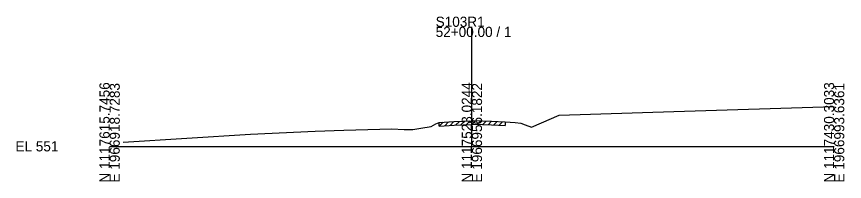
# Model space of a CAD drawing. Extents: x -26 to 203, y -10 to 12018.
# Drawn here: x -25.7 to 202.8, y 490.3 to 535.8 of the extents above; entities that cross this region are included whole.
import ezdxf

# ---------------------------------------------------------------- set-up
doc = ezdxf.new("R2010")
doc.units = 0
for name, color, linetype in [('Level 60', 7, 'Continuous'), ('Level 61', 7, 'Continuous'), ('Level 63', 7, 'Continuous')]:
    doc.layers.add(name, color=color, linetype=linetype)

msp = doc.modelspace()

# ---------------------------------------------------------------- linework, layer by layer
at = {"layer": 'Level 60'}
for p, q in [((155.79, 509.61), (200, 511)), ((119.19, 506.49), (124.1, 508.61)), ((124.1, 508.61), (155.79, 509.61)), ((85.87, 505), (88.79, 505.51)), ((88.79, 505.51), (90.06, 506.19)), ((90.06, 506.19), (90.99, 506.61)), ((90.99, 506.61), (95.14, 506.83)), ((95.14, 506.83), (100, 507.07)), ((100, 507.07), (100.44, 507.09)), ((100.44, 507.09), (105.43, 506.91)), ((105.43, 506.91), (109.23, 506.78)), ((109.23, 506.78), (111.9, 506.56)), ((111.9, 506.56), (113.5, 506.43)), ((113.5, 506.43), (114.7, 505.97)), ((114.7, 505.97), (116.41, 505.28)), ((116.41, 505.28), (119.19, 506.49)), ((3.71, 501.14), (38.93, 503.4)), ((38.93, 503.4), (56.78, 504.22)), ((56.78, 504.22), (64.69, 504.45)), ((64.69, 504.45), (77.92, 504.85)), ((77.92, 504.85), (81.31, 504.69)), ((81.31, 504.69), (83.67, 504.61)), ((83.67, 504.61), (85.87, 505))]:
    msp.add_line(p, q, dxfattribs=at)
at = {"layer": 'Level 61'}
for p, q in [((90.99, 505.61), (92.04, 506.66)), ((90.99, 505.61), (90.99, 506.61)), ((90.99, 505.61), (95.14, 505.83)), ((92.49, 505.69), (93.54, 506.74)), ((93.99, 505.77), (95.04, 506.82)), ((95.14, 505.83), (100, 506.07)), ((95.49, 505.84), (96.54, 506.9)), ((96.99, 505.92), (98.04, 506.97)), ((98.49, 505.99), (99.54, 507.05)), ((99.99, 506.07), (100.99, 507.07)), ((100, 506.07), (100.44, 506.09)), ((100.44, 506.09), (105.43, 505.91)), ((101.49, 506.05), (102.45, 507.02)), ((102.99, 506), (103.95, 506.96)), ((104.49, 505.94), (105.45, 506.91)), ((105.43, 505.91), (109.23, 505.78)), ((105.99, 505.89), (106.95, 506.86)), ((107.49, 505.84), (108.45, 506.8)), ((109.23, 506.78), (109.23, 505.78))]:
    msp.add_line(p, q, dxfattribs=at)
at = {"layer": 'Level 63'}
for p, q in [((100, 500), (100, 533)), ((0, 500), (100, 500)), ((100, 500), (200, 500))]:
    msp.add_line(p, q, dxfattribs=at)

# ---------------------------------------------------------------- texts
for s, p in [('S103R1', (90, 533)), ('52+00.00 / 1', (90, 530.2)), ('EL 551', (-26, 498.6))]:
    msp.add_text(s, height=2.8, dxfattribs=at).set_placement(p)
for s, p in [('N 1117615.7456', (0, 490)), ('E 1966918.7283', (2.8, 490)), ('N 1117523.0244', (100, 490)), ('E 1966956.1822', (102.8, 490)), ('N 1117430.3033', (200, 490)), ('E 1966993.6361', (202.8, 490))]:
    msp.add_text(s, height=2.8, rotation=90, dxfattribs=at).set_placement(p)

doc.saveas('drawing.dxf')
